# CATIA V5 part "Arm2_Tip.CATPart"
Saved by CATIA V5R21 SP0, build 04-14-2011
Part number: Arm2_Tip
Bounding box of the stored display mesh (mm): x 0 to 13, y -12.5 to 12.5, z -12.409 to 12.409
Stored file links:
  K:\Arm_Detailed_Design_Assembly_Manu\Arm2_Tip.CATPart
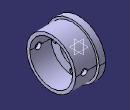
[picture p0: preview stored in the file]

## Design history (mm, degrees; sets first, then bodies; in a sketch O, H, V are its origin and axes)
Body1 (main body)
  Sketch1 on yz-plane, origin (0, 0, 0), H (0, 1, 0), V (0, 0, 1)
    circle A1 centre (0, 0) radius 12.5
    circle A2 centre (0, 8.5) radius 1.25
    point P1 (0, 8.5)
    circle A3 centre (-8.5, 0) radius 1.25
    circle A4 centre (0, -8.5) radius 1.25
    circle A5 centre (8.5, 0) radius 1.25
    circle A6 centre (0, 0) radius 6
    radius A1 = 12.5
    radius A2 = 1.25
    distance H P1 = 8.5
    radius A6 = 6
    coincidence: P1 V
  Pad1: profile Sketch1, direction (1, 0, 0), length 3
  Sketch2 on end face of Pad1, origin (3, 0, 0), H (0, 1, 0), V (0, 0, 1)
    circle A1 centre (0, 0) radius 11.5
    circle A2 centre (0, 0) radius 10
    radius A1 = 11.5
    radius A2 = 10
  Pad2: profile Sketch2, direction (1, 0, 0), length 10
  Sketch3 on zx-plane, origin (0, 0, 0), H (-1, 0, 0), V (0, 0, 1)
    circle A1 centre (-9, 0) radius 1.5
    point P1 (-9, 0)
    reference projected line E1 (-3, -12.5) -> (-3, 12.5) from edge [face of Pad1 from Sketch1.A1 | end face of Pad1]
    distance E1 P1 = 6
    radius A1 = 1.5
    coincidence: P1 H
  Pocket1: profile Sketch3, direction (0, 1, 0), length 20, mirrored extent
